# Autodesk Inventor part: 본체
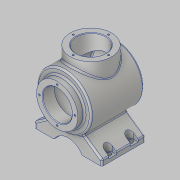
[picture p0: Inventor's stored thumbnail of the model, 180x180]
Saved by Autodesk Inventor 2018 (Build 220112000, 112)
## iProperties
Created: 2021-04
Part Number: 본체
Material: 알루미늄 6061
Document SubType Name: Modeling
Designer: home
Density: 2.7 g/cm^3
Appearance: 알루미늄 - 평지
Mass: 1640.8 g
Surface Area: 1043.97 cm^2
Volume: 607.702 cm^3
Author: home
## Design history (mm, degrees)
sketch "스케치2"
  geometry: L1 (77, 20)-(77, -100); L2 (104, 20)-(115, 20); L3 (115, 20)-(115, 11); L4 (118, 8)-(124, 8); L5 (127, 5)-(127, -86.454); L6 (104, 20)-(104, -2); L7 (104, -2)-(117, -2); L8 (117, -2)-(117, -79.903); A1 r 113 centre (77, 13) between (77, -100) and (125.282, -89.166); A2 r 3 centre (124, -86.454) between (125.282, -89.166) and (127, -86.454); A3 r 3 centre (124, 5) between (127, 5) and (124, 8); A4 r 3 centre (118, 11) between (115, 11) and (118, 8); A5 r 103 centre (77, 13) between (77, -90) and (115.11, -82.69); A6 r 3 centre (114, -79.903) between (115.11, -82.69) and (117, -79.903); 3 further points
  constraints: 16 end point, 14 point on circle, 8 tangent, 6 centre point, 5 perpendicular, 3 point on line, 2 vertical, 1 equal radius, 1 horizontal, 1 horizontal alignment, 1 vertical alignment
  dimensions: "d2" = 77 distance from line of L1 point (0, 0); "d3" = 20 vertical distance of point (0, 0) L1.start; "d4" = 76 diameter of L3 L1; "d5" = 100 diameter of L5 L1; "d6" = 12 distance between parallel lines of L4 L2; "d7" = 226 diameter of A1; "d8" = 108 distance from line of L1.end L4; "d9" = 3 radius of A2; "d10" = 3 radius of A3 (derived); "d11" = 10 radial gap between concentric circles of A1 A5; "d12" = 54 diameter of L6 L1; "d13" = 80 diameter of L8 L1; "d14" = 22 distance between parallel lines of L7 L2; "d15" = 3 radius of A6 (derived)
revolve "회전1" sketch "스케치2" stored, may be unused: angle "d16" = 90 deg
node "작업 평면1"
sketch "스케치3"
  geometry: L1 (-38, 20)-(38, 20) reference; C1 r 38 at (0, -42); 1 further point
  constraints: 1 centre point, 1 vertical alignment
  dimensions: "d18" = 76 diameter of C1; "d19" = 62 distance from line of C1.centre L1
extrude "돌출1" join sketch "스케치3" stored distance "d20" = 10; taper "d21" = 0 deg
hole "구멍1" diameter "d24" = 54; stored, may be unused: countersink angle "d28" = 90 deg, drill point angle "d30" = 118 deg; dims "d22" = 10, "d23" = 10, "d25" = 6, "d26" = 4, "d27" = 2, "d29" = 51.5
sketch "스케치4"
  geometry: C1 r 38 at (0, 0) reference; C2 r 27 at (0, 0) reference; 2 further points
  constraints: 1 vertical alignment
  dimensions: "d31" = 32.5 distance of point (0, 32.5) C1.centre
hole "구멍2" sketch "스케치4" at (0, 32.5) diameter "d32" = 3.242; stored, may be unused: countersink angle "d36" = 90 deg, drill point angle "d38" = 118 deg; dims "d33" = 8, "d34" = 4, "d35" = 2, "d37" = 10
sketch "스케치5"
  geometry: C1 r 27 at (0, 0) reference; C2 r 38 at (0, 0) reference; 2 further points
  constraints: 1 horizontal alignment
  dimensions: "d42" = 32.5 distance of point (-32.5, 0) C1.centre
hole "구멍3" sketch "스케치5" at (-32.5, 0) diameter "d43" = 3.242; stored, may be unused: countersink angle "d47" = 90 deg, drill point angle "d49" = 118 deg; dims "d44" = 8, "d45" = 4, "d46" = 2, "d48" = 10
node "작업 평면4"
sketch "스케치7"
  geometry: L1 (-62, -77)-(-62, -67); L2 (-62, -67)-(-26.694, -42.278); L3 (-62, -67)-(-18.899, -67); L4 (-62, -77)-(-25.981, -77); L5 (25.981, -77)-(62, -77); L6 (62, -77)-(62, -67); L7 (62, -67)-(105.101, -67); L8 (62, -67)-(26.694, -42.278); L9 (62, -67)-(105.101, -67); A1 r 50 centre (0, 0) between (-26.694, -42.278) and (26.694, -42.278) reference; A2 r 30 centre (0, -92) between (25.981, -77) and (-25.981, -77); A3 r 50 centre (0, 0) between (-26.694, -42.278) and (26.694, -42.278); 3 further points
  constraints: 18 end point, 7 point on circle, 5 horizontal, 2 centre point, 2 coincident, 2 equal length, 2 horizontal alignment, 2 vertical, 2 vertical alignment, 1 concentric
  dimensions: "d56" = 124 distance of L1.start L5.end; "d57" = 10 distance of L1.start L1.end; "d58" = 35 deg angle of L3 L2; "d59" = 60 diameter of A2; "d61" = 15 distance of point (0, -62) point (0, -77); "d62" = 62 distance from line of point (0, -77) L1; "d64" = 145 deg angle of L9 L8; "d65" = 10 distance of L5.end L6.end
extrude "돌출2" join sketch "스케치7" distance "d66" = 80; taper "d67" = 0 deg
node "작업 평면5"
sketch "스케치8"
  geometry: L1 (-25.981, 0)-(-62, 0) reference; L2 (-25.981, 0)-(-25.981, -80) reference; L3 (-62, -80)-(-25.981, -80) reference; L4 (-62, 0)-(-62, -80) reference; L5 (-54, -53)-(-62, -53); L6 (-54, -67)-(-62, -67); L7 (-62, -53)-(-62, -67); A1 r 7 centre (-54, -60) between (-54, -67) and (-54, -53); 1 further point
  constraints: 6 end point, 2 perpendicular, 2 point on circle, 2 point on line, 2 tangent, 1 centre point, 1 collinear
  dimensions: "d69" = 14 diameter of A1; "d70" = 20 distance from line of A1.centre L3; "d71" = 8 distance from line of A1.centre L4
extrude "돌출3" cut sketch "스케치8" distance "d72" = 28.75; taper "d73" = 0 deg
sketch "스케치9"
  geometry: L1 (8, 40)-(0, 40) reference; L2 (0, 54)-(8, 54) reference; L3 (0, 40)-(0, 54) reference; L4 (8, 0)-(0, 0) reference; L5 (0, 14)-(8, 14) reference; L6 (0, 0)-(0, 14) reference; L7 (116, 40)-(124, 40) reference; L8 (124, 54)-(124, 40) reference; L9 (124, 54)-(116, 54) reference; L10 (116, 0)-(124, 0) reference; L11 (124, 14)-(124, 0) reference; L12 (124, 14)-(116, 14) reference; A1 r 7 centre (8, 47) between (8, 40) and (8, 54) reference; A2 r 7 centre (8, 7) between (8, 0) and (8, 14) reference; A3 r 7 centre (116, 47) between (116, 54) and (116, 40) reference; A4 r 7 centre (116, 7) between (116, 14) and (116, 0) reference; 1 further point
hole "구멍4" sketch "스케치9" at (8, 7), (8, 47), (116, 47), (116, 7) diameter "d77" = 9; stored, may be unused: countersink angle "d81" = 90 deg, drill point angle "d83" = 118 deg; dims "d78" = 8, "d79" = 4, "d80" = 2, "d82" = 10
chamfer "모따기1" distance "d84" = 1; stored, may be unused: second distance "d85" = 2, angle "d86" = 45 deg
fillet "모깎기1" dims "d87" = 3
node "작업 평면9"
node "작업 평면10"
sketch "스케치13"
  geometry: L1 (-38, 65)-(38, 65) reference; 2 further points
  constraints: 1 vertical alignment, 1 other
  dimensions: "d96" = 77 distance of point (0, 0) point (0, -77)
feature "엠보싱2" sketch "스케치13" dims "d97" = 0.5, "d98" = 0
node "솔리드1"
pattern_circular "원형 패턴1" dims angle "d40" = 360 deg
pattern_circular "원형 패턴2" dims angle "d51" = 360 deg
pattern_linear "직사각형 패턴1" dims "d76" = 40
mirror "미러1"
node "투영된 루프1"
node "투영된 루프2"
node "투영된 루프3"
node "투영된 루프4"
node "투영된 루프5"
node "투영된 루프6"
node "투영된 루프7"
other parameters: "d17" = 142, "d60" = 15, "d68" = 6, "d90" = -120.5, "d94" = 197.25
